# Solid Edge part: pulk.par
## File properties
Author: Mac
Template: Normal.par
Last saved by: Mac
Revision: 5
Application: Solid Edge
Material: Stainless steel
Face Style: Steel
Fill Style: ANSI32(Steel)
Virtual Style: Stainless steel
Coef. of Thermal Exp: 1.6e-05
Thermal Conductivity: 17.0
Specific Heat: 502.0
Modulus of Elasticity: 193053196000.0
Poission's Ratio: 0.29
Yield Stress: 310264065.0
Ultimate Stress: 641212401.0
Elongation: 0.0
Density: 7750,000 kg/m^3
Accuracy: 0,990
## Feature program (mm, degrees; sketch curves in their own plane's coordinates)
sketch for "unnamed Protrusion 1" plane through (0, 0, 0) normal (0, -1, 0) x-axis (1, 0, 0)
  line (-0.0751, 0.13) -> (0.0751, 0.13)
  line (0.0751, 0.13) -> (0.1501, 0)
  line (0.1501, 0) -> (0.0751, -0.13)
  line (-0.0751, -0.13) -> (0.0751, -0.13)
  line (-0.0751, -0.13) -> (-0.1501, 0)
  line (-0.1501, 0) -> (-0.0751, 0.13)
  dimension (linear) = 0.1501
extrude "unnamed Protrusion 1" add finite 0.05 along +normal
sketch for "unnamed RevolvedCutout 1" plane through (0, 0, 0) normal (0, 0, 1) x-axis (1, 0, 0)
  line (0.1501, 0) -> (0.1501, -0.03)
  line (0.1501, -0.03) -> (0.1301, -0.05)
  line (0.1301, -0.05) -> (0, -0.05)
  line (0.1572, -0.0589) -> (0, -0.0589)
  line (0.1572, 0) -> (0.1572, -0.0589)
  line (0.1501, 0) -> (0.1572, 0)
revolve "unnamed RevolvedCutout 1" cut full turn 360 deg about sketch line (0, -0.0589) -> (0, -0.05)
body pattern "unnamed BodyPattern 1"
pattern "unnamed Pattern 1"
sketch for "ExtrudedCutout_1" plane through (0, -0.05, 0) normal (0, -1, 0) x-axis (1, 0, 0)
  circle centre (0, 0) radius 0.1119
extrude "ExtrudedCutout_1" cut finite 0.02 along -normal
fillet "Round_1" radius 0.01
sketch for "ExtrudedProtrusion_3" #5 plane through (0, -0.03, 0) normal (0, -1, 0) x-axis (1, 0, 0)
extrude "ExtrudedProtrusion_3" add finite 0.01 along +normal
sketch for "ExtrudedProtrusion_4" plane through (0, 0.05, 0) normal (0, 1, 0) x-axis (-1, 0, 0)
  circle centre (0, 0) radius 0.08
extrude "ExtrudedProtrusion_4" add finite 1.75 along +normal
sketch for "unnamed Cutout 1" plane through (0, 0, 0) normal (0, 0, 1) x-axis (1, 0, 0)
  circle centre (0, 1.62) radius 0.025
extrude "unnamed Cutout 1" cut to key point symmetric
chamfer "unnamed Chamfer 1"
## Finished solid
Body 1: solid body, 90 faces, 230 edges, 146 vertices.
  Faces by surface: plane 49, swept 21, cone 14, cylinder 2, spline 2, torus 2
  Edges by curve: spline 110, line 73, intersection 24, circle 19, curve on surface 4
Bounding box of the edges (mm; curved faces can reach further): 0.300 x 1.850 x 0.260, from (-0.1501, -0.05, -0.13) to (0.1501, 1.8, 0.13).
Cylindrical faces by radius (mm): R0.025 x1, R0.08 x1
Conical faces (half-angle, radius in mm at the cone's reference point): 45 deg R0.08 x1, 45 deg R0.09 x1, 45 deg R0.1501 x12
Toroidal faces (ring radius, tube radius in mm): R0.1019 r0.01 x1, R0.1219 r0.01 x1
Planar faces by outward normal: +x 8, +y 2, +z 2, -x 10, -y 7, -z 6, oblique 14
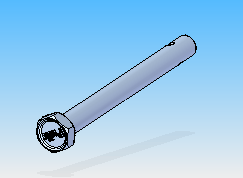
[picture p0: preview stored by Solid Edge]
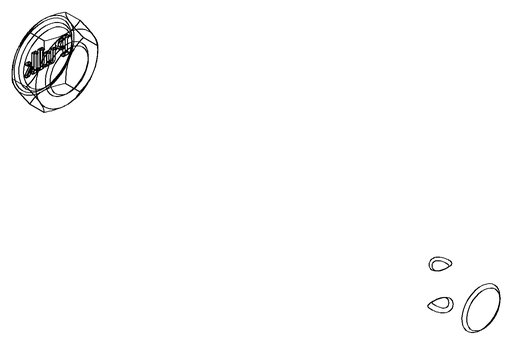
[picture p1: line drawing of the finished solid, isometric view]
